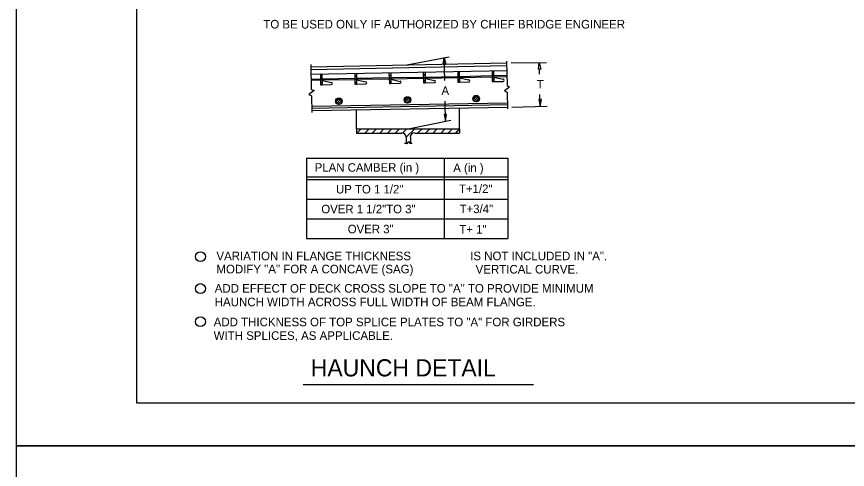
# Model space of a CAD drawing. Extents: x -24512 to -22484, y 4569 to 6351.
# Drawn here: x -24179.8 to -23889.5, y 5748.8 to 5907.1 of the extents above; entities that cross this region are included whole.
import ezdxf

# ---------------------------------------------------------------- set-up
doc = ezdxf.new("R2010")
doc.units = 0
for name, color, linetype in [('10', 7, 'Continuous'), ('11', 7, 'Continuous'), ('2', 7, 'Continuous'), ('4', 7, 'Continuous'), ('5', 7, 'Continuous'), ('6', 7, 'Continuous'), ('PLT-BNDY', 7, 'Continuous')]:
    doc.layers.add(name, color=color, linetype=linetype)

# ---------------------------------------------------------------- blocks, each defined once
blk = doc.blocks.new('JUQ005')
at = {"layer": '4'}
for p, q in [((12.764875, 6.492125), (12.825, 6.552375)), ((12.764875, 6.207), (12.916, 6.35825)), ((12.764875, 5.921875), (12.916, 6.073125)), ((12.764875, 5.63675), (12.916, 5.788))]:
    blk.add_line(p, q, dxfattribs=at)
blk = doc.blocks.new('JUQ006')
at = {"layer": '4'}
for p, q in [((10.418625, 11.48775), (10.630375, 11.699625)), ((10.457, 11.312375), (10.805875, 11.66125)), ((10.574625, 11.21625), (10.902, 11.5435)), ((10.82875, 11.256375), (10.86175, 11.2895))]:
    blk.add_line(p, q, dxfattribs=at)

msp = doc.modelspace()

# ---------------------------------------------------------------- linework, layer by layer
at = {"layer": '10'}
for p, q in [((-24043.43, 5890.21), (-24028.59, 5893.07)), ((-24030.21, 5884.72), (-24030.34, 5892.82)), ((-24007.02, 5890.95), (-23994.68, 5891.08)), ((-23997.05, 5886.96), (-23997.05, 5888.71)), ((-24029.97, 5870.5), (-24030.09, 5877.49)), ((-23996.8, 5875.74), (-23996.92, 5879.86)), ((-24006.77, 5875.49), (-23994.43, 5875.74)), ((-24042.93, 5867.89), (-24028.09, 5870.88)), ((-24078.43, 5857.61), (-24078.43, 5829.49)), ((-24078.43, 5857.61), (-24008.14, 5857.61)), ((-24030.42, 5857.61), (-24030.42, 5829.49)), ((-24008.14, 5857.61), (-24008.14, 5829.49)), ((-24078.43, 5851.1), (-24007.86, 5851.1)), ((-24078.43, 5850.17), (-24007.95, 5850.17)), ((-24078.43, 5843.27), (-24008.04, 5843.27)), ((-24078.43, 5836.38), (-24008.14, 5836.38)), ((-24078.43, 5829.49), (-24008.14, 5829.49))]:
    msp.add_line(p, q, dxfattribs=at)
for points in [[(-24029.84, 5890.33), (-24030.71, 5890.33), (-24030.34, 5892.82)], [(-23996.67, 5888.71), (-23997.42, 5888.71), (-23997.17, 5891.08)], [(-23996.42, 5878.11), (-23997.3, 5878.11), (-23996.8, 5875.74)], [(-24029.59, 5872.87), (-24030.34, 5872.87), (-24029.97, 5870.5)]]:
    msp.add_lwpolyline(points, close=True, dxfattribs=at)
for centre in [(-24115.53, 5823.21), (-24115.53, 5812.03), (-24115.53, 5800.47)]:
    msp.add_circle(centre, 1.73, dxfattribs=at)
at = {"layer": '11'}
msp.add_line((-23999.14, 5778.43), (-24079.61, 5778.43), dxfattribs=at)
at = {"layer": '2'}
for p, q in [((-24137.79, 5772.04), (-24137.79, 6334.63)), ((-23353.75, 5772.04), (-24137.79, 5772.04))]:
    msp.add_line(p, q, dxfattribs=at)
at = {"layer": '5'}
for p, q in [((-24076.97, 5889.58), (-24008.52, 5890.95)), ((-24076.97, 5888.58), (-24008.52, 5889.96)), ((-24076.85, 5886.96), (-24008.52, 5888.21)), ((-24073.61, 5887.09), (-24073.61, 5883.22)), ((-24073.11, 5887.09), (-24072.98, 5883.22)), ((-24061.64, 5887.34), (-24061.64, 5883.47)), ((-24061.01, 5887.34), (-24061.01, 5883.47)), ((-24061.01, 5885.59), (-24049.67, 5885.84)), ((-24049.67, 5887.46), (-24049.54, 5883.72)), ((-24049.04, 5887.46), (-24049.04, 5883.72)), ((-24049.04, 5885.84), (-24037.57, 5885.97)), ((-24037.7, 5887.71), (-24037.57, 5883.97)), ((-24037.07, 5887.71), (-24037.07, 5883.97)), ((-24037.07, 5885.97), (-24025.6, 5886.22)), ((-24037.07, 5885.59), (-24025.6, 5885.84)), ((-24025.6, 5887.96), (-24025.6, 5884.22)), ((-24025.1, 5887.96), (-24024.98, 5884.22)), ((-24025.1, 5886.22), (-24013.63, 5886.46)), ((-24025.1, 5885.84), (-24013.63, 5886.09)), ((-24013.63, 5888.09), (-24013.63, 5884.47)), ((-24013.13, 5888.09), (-24013.01, 5884.47)), ((-24013.01, 5886.46), (-24008.39, 5886.59)), ((-24013.01, 5886.09), (-24008.39, 5886.22)), ((-24013.01, 5885.97), (-24009.77, 5885.22)), ((-24076.85, 5885.22), (-24073.61, 5885.34)), ((-24076.85, 5884.97), (-24073.61, 5884.97)), ((-24073.61, 5883.22), (-24072.98, 5883.22)), ((-24072.98, 5885.34), (-24061.64, 5885.59)), ((-24072.98, 5884.97), (-24061.64, 5885.09)), ((-24072.98, 5884.72), (-24069.74, 5884.1)), ((-24072.98, 5883.22), (-24069.87, 5883.35)), ((-24061.64, 5883.47), (-24061.01, 5883.47)), ((-24061.01, 5885.22), (-24049.67, 5885.34)), ((-24061.01, 5884.97), (-24057.77, 5884.35)), ((-24061.01, 5883.47), (-24057.9, 5883.6)), ((-24049.54, 5883.72), (-24049.04, 5883.72)), ((-24049.04, 5885.34), (-24037.57, 5885.59)), ((-24049.04, 5885.22), (-24045.8, 5884.47)), ((-24049.04, 5883.72), (-24045.8, 5883.85)), ((-24037.57, 5883.97), (-24037.07, 5883.97)), ((-24037.07, 5885.47), (-24033.71, 5884.72)), ((-24037.07, 5883.97), (-24033.83, 5884.1)), ((-24025.6, 5884.22), (-24024.98, 5884.22)), ((-24025.1, 5885.72), (-24021.74, 5884.97)), ((-24024.98, 5884.22), (-24021.86, 5884.35)), ((-24013.63, 5884.47), (-24013.01, 5884.47)), ((-24013.01, 5884.47), (-24009.77, 5884.47)), ((-24076.6, 5875.74), (-24008.27, 5876.99)), ((-24076.6, 5875.12), (-24008.27, 5876.37)), ((-24076.6, 5874.25), (-24008.27, 5875.49)), ((-24061.01, 5867.89), (-24061.01, 5874.49)), ((-24024.98, 5867.89), (-24024.98, 5875.12)), ((-24061.01, 5867.89), (-24024.98, 5867.89)), ((-24061.01, 5867.89), (-24061.01, 5866.39)), ((-24061.01, 5866.39), (-24045.18, 5866.39)), ((-24040.69, 5866.39), (-24024.98, 5866.39)), ((-24024.98, 5867.89), (-24024.98, 5866.39)), ((-24044.3, 5862.9), (-24043.43, 5862.9)), ((-24043.68, 5864.89), (-24043.68, 5862.9)), ((-24043.43, 5862.9), (-24043.31, 5862.65)), ((-24043.31, 5862.65), (-24042.68, 5863.4)), ((-24042.68, 5863.4), (-24042.43, 5862.9)), ((-24042.43, 5862.9), (-24041.56, 5862.9)), ((-24042.18, 5864.89), (-24042.18, 5862.9))]:
    msp.add_line(p, q, dxfattribs=at)
for points in [[(-24008.64, 5891.58), (-24008.39, 5882.97), (-24007.52, 5882.47), (-24009.27, 5881.1), (-24008.39, 5880.73), (-24008.27, 5874.87)], [(-24076.97, 5890.33), (-24076.85, 5881.6), (-24075.85, 5881.23), (-24077.72, 5879.86), (-24076.72, 5879.36), (-24076.6, 5873.62)]]:
    msp.add_lwpolyline(points, dxfattribs=at)
for centre, radius in [((-24067.19, 5877.52), 1.13), ((-24067.18, 5877.33), 0.938), ((-24043.19, 5877.98), 1.13), ((-24043.18, 5877.79), 0.938), ((-24019.19, 5878.44), 1.13), ((-24019.19, 5878.25), 0.938)]:
    msp.add_circle(centre, radius, dxfattribs=at)
for centre, radius, start, end in [((-24069.82, 5883.71), 0.375, 271.0964, 77.9991), ((-24057.82, 5883.94), 0.375, 271.0964, 77.9991), ((-24045.82, 5884.17), 0.375, 271.0964, 77.9991), ((-24033.83, 5884.39), 0.375, 271.0964, 77.9991), ((-24021.83, 5884.62), 0.375, 271.0964, 77.9991), ((-24009.83, 5884.85), 0.375, 271.0964, 77.9991), ((-24045.22, 5864.94), 1.5, 0, 90), ((-24040.72, 5864.94), 1.5, 90, 180)]:
    msp.add_arc(centre, radius, start, end, dxfattribs=at)
at = {"layer": '6'}
for p, q in [((-24060.89, 5866.39), (-24059.39, 5867.89)), ((-24058.14, 5866.39), (-24056.65, 5867.89)), ((-24055.53, 5866.39), (-24054.03, 5867.89)), ((-24052.91, 5866.39), (-24051.41, 5867.89)), ((-24050.16, 5866.39), (-24048.67, 5867.89)), ((-24047.55, 5866.39), (-24046.05, 5867.89)), ((-24044.93, 5866.39), (-24043.43, 5867.89)), ((-24043.68, 5865.02), (-24040.69, 5867.89)), ((-24039.69, 5866.39), (-24038.07, 5867.89)), ((-24036.95, 5866.39), (-24035.45, 5867.89)), ((-24034.33, 5866.39), (-24032.83, 5867.89)), ((-24031.59, 5866.39), (-24030.09, 5867.89)), ((-24028.97, 5866.39), (-24027.47, 5867.89)), ((-24026.35, 5866.39), (-24024.98, 5867.89))]:
    msp.add_line(p, q, dxfattribs=at)
at = {"layer": 'PLT-BNDY'}
for points in [[(-23338.75, 5757.04), (-24179.75, 5757.04), (-24179.75, 6351.04), (-23338.75, 6351.04)], [(-24179.75, 5757.04), (-23338.75, 5757.04), (-23338.75, 5163.04), (-24179.75, 5163.04)]]:
    msp.add_lwpolyline(points, close=True, dxfattribs=at)

# ---------------------------------------------------------------- block references
at = {"layer": '4', "xscale": 3.720483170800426, "yscale": 3.720483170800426, "rotation": 1.0964384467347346}
for name, p in [('JUQ005', (-24120.74, 5861.78)), ('JUQ005', (-24108.64, 5861.9)), ('JUQ005', (-24096.67, 5862.15)), ('JUQ005', (-24084.7, 5862.4)), ('JUQ005', (-24072.61, 5862.65)), ('JUQ005', (-24060.64, 5862.9)), ('JUQ006', (-24106.02, 5833.97)), ('JUQ006', (-24081.96, 5834.47)), ('JUQ006', (-24058.02, 5834.84))]:
    msp.add_blockref(name, p, dxfattribs=at)

# ---------------------------------------------------------------- texts
at = {"layer": '10'}
for s, height, p in [('TO BE USED ONLY IF AUTHORIZED BY CHIEF BRIDGE ENGINEER', 3, (-24093.57, 5902.95)), ('T', 3, (-23998.04, 5881.98)), ('A', 3, (-24031.34, 5879.73)), ('PLAN CAMBER (in )', 2.977, (-24075.61, 5852.88)), ('A (in )', 2.977, (-24027.22, 5852.78)), ('UP TO 1 1/2"', 2.9771, (-24068.18, 5845.29)), ('T+1/2"', 2.977, (-24025.22, 5845.43)), ('OVER 1 1/2"TO 3"', 2.9771, (-24073.31, 5838.34)), ('T+3/4"', 2.977, (-24025, 5838.41)), ('OVER 3"', 2.977, (-24064.07, 5831.36)), ('T+ 1"', 2.977, (-24025.09, 5831.27)), ('VARIATION IN FLANGE THICKNESS', 3, (-24109.96, 5821.94)), ('IS NOT INCLUDED IN "A".', 3, (-24021.31, 5821.95)), ('MODIFY "A" FOR A CONCAVE (SAG)', 3, (-24109.96, 5817.35)), ('VERTICAL CURVE.', 3, (-24019.4, 5817.3)), ('ADD EFFECT OF DECK CROSS SLOPE TO "A" TO PROVIDE MINIMUM', 3, (-24110.54, 5810.62)), ('HAUNCH WIDTH ACROSS FULL WIDTH OF BEAM FLANGE.', 3, (-24110.54, 5805.87)), ('ADD THICKNESS OF TOP SPLICE PLATES TO "A" FOR GIRDERS', 3, (-24110.91, 5798.86)), ('WITH SPLICES, AS APPLICABLE.', 3, (-24110.91, 5794.11))]:
    msp.add_text(s, height=height, dxfattribs=at).set_placement(p)
at = {"layer": '11'}
msp.add_text('HAUNCH DETAIL', height=6.0008, dxfattribs=at).set_placement((-24076.99, 5781.34))

doc.saveas('drawing.dxf')
